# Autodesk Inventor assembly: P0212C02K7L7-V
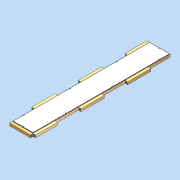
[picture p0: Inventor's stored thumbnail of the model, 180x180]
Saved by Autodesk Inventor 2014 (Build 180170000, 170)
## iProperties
Created: 2011-04
Part Number: P0212C02K7L7-V
Document SubType Name: Assembly
Designer: david.appleford
Description: 0.5w x 3w 02 Ceiling Panel 8 Locks 7 Lugs
Mass: 46000 g
Surface Area: 57548 cm^2
Volume: 179370 cm^3
Density: 0.256453 g/cm^3
Cost Center: £174.00
Justset: False
Author: david.appleford
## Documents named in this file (5)
- C:\Documents and Settings\john.everitt\Local Settings\My Documents\Vault\Production MkII\VIRTUAL ELEMENTS\Virtual Ceilings\Ceiling MgO & Timber Frame\P0212C02K8L7-V.iam
- C:\Documents and Settings\john.everitt\Local Settings\My Documents\Vault\Production MkII\VIRTUAL ELEMENTS\Virtual Lugs\Superceded Lugs\LA02C3V.ipt
- C:\Documents and Settings\john.everitt\Local Settings\My Documents\Vault\Production MkII\VIRTUAL ELEMENTS\Virtual Lugs\Superceded Lugs\LA02M3V.ipt
- C:\Documents and Settings\john.everitt\Local Settings\My Documents\Vault\Production MkII\VIRTUAL ELEMENTS\Virtual Lugs\Superceded Lugs\LA02E3V.ipt
- C:\Documents and Settings\john.everitt\Local Settings\My Documents\Vault\Production MkII\VIRTUAL ELEMENTS\Virtual Ceilings\Ceiling MgO & Timber Frame\P0212C02K8-V.ipt
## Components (8 placed, 4 different names)
1. P0212C02K8-V:1 — Mate:1, Flush:1, Flush:2, Mate:2, Flush:3, Flush:4, Mate:3, Flush:5, Flush:6, Mate:5, Mate:6, Flush:9, Flush:10, Mate:7, Mate:8, Flush:11, Flush:12
2. LA02C3V:1 — Mate:1, Flush:1, Flush:2, Mate:9
3. LA02E3V:1 — Mate:2, Flush:3, Flush:4
4. LA02C3V:4 — Mate:3, Flush:5, Flush:6, Mate:11
5. LA02M3V:1 — Mate:6, Flush:9, Mate:11, Mate:12
6. LA02M3V:2 — Mate:5, Flush:10, Mate:12
7. LA02M3V:3 — Mate:8, Flush:12, Mate:10
8. LA02M3V:4 — Mate:7, Flush:11, Mate:9, Mate:10
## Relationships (21: Mate 11, Flush 10)
- Mate:1: P0212C02K8-V:1 ↔ LA02C3V:1
- Flush:1: P0212C02K8-V:1 ↔ LA02C3V:1
- Flush:2: P0212C02K8-V:1 ↔ LA02C3V:1
- Mate:2: P0212C02K8-V:1 ↔ LA02E3V:1
- Flush:3: P0212C02K8-V:1 ↔ LA02E3V:1
- Flush:4: P0212C02K8-V:1 ↔ LA02E3V:1
- Mate:3: P0212C02K8-V:1 ↔ LA02C3V:4
- Flush:5: P0212C02K8-V:1 ↔ LA02C3V:4
- Flush:6: P0212C02K8-V:1 ↔ LA02C3V:4
- Mate:5: P0212C02K8-V:1 ↔ LA02M3V:2
- Mate:6: P0212C02K8-V:1 ↔ LA02M3V:1
- Flush:9: P0212C02K8-V:1 ↔ LA02M3V:1
- Flush:10: P0212C02K8-V:1 ↔ LA02M3V:2
- Mate:7: P0212C02K8-V:1 ↔ LA02M3V:4
- Mate:8: P0212C02K8-V:1 ↔ LA02M3V:3
- Flush:11: P0212C02K8-V:1 ↔ LA02M3V:4
- Flush:12: P0212C02K8-V:1 ↔ LA02M3V:3
- Mate:9: LA02C3V:1 ↔ LA02M3V:4
- Mate:10: LA02M3V:3 ↔ LA02M3V:4
- Mate:11: LA02C3V:4 ↔ LA02M3V:1
- Mate:12: LA02M3V:1 ↔ LA02M3V:2
## Named parameters: t = 1 mm, Cl = 2 mm
